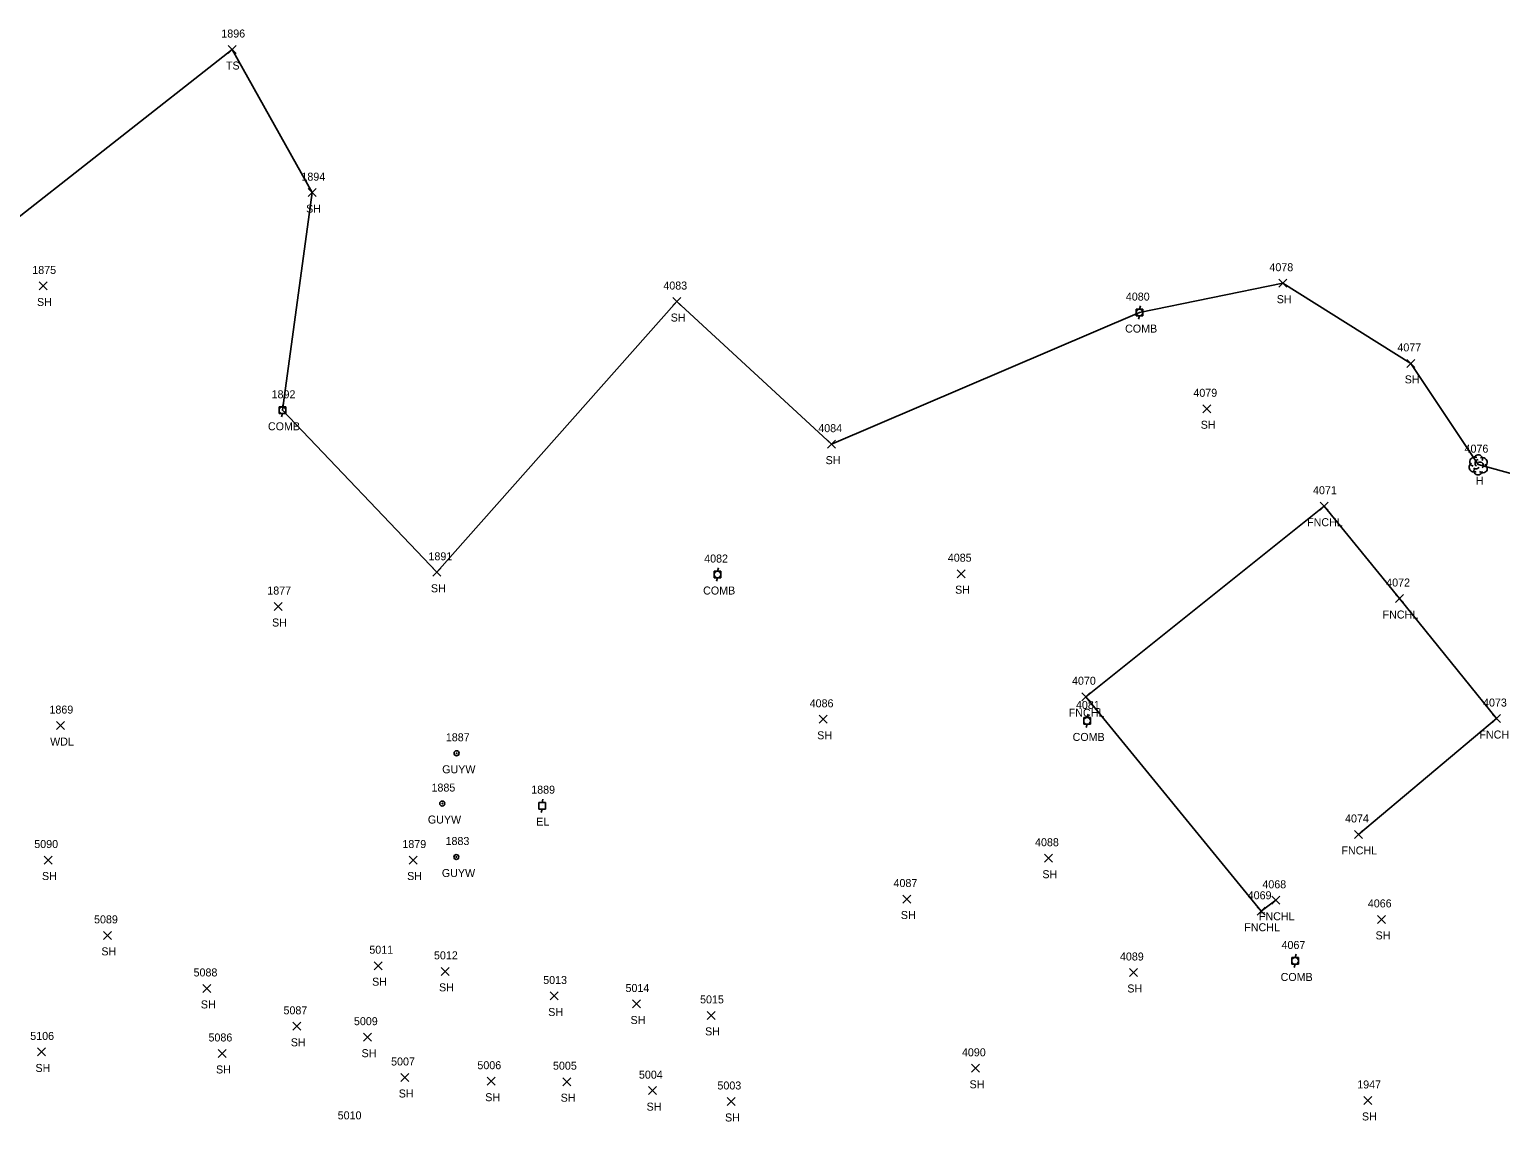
# Model space of a CAD drawing. Extents: x 1509053 to 1511576, y 400838 to 402572.
# Drawn here: x 1510281.3 to 1510649, y 401737.3 to 402010.4 of the extents above; entities that cross this region are included whole.
import ezdxf

# ---------------------------------------------------------------- set-up
doc = ezdxf.new("R2010")
doc.units = 0
for name, color, linetype in [('L_A', 7, 'Continuous'), ('L_I', 7, 'Continuous'), ('L_TIC', 7, 'Continuous'), ('LELB', 7, 'Continuous'), ('LFNC', 7, 'Continuous'), ('LSOGP', 7, 'Continuous'), ('LTD', 7, 'Continuous'), ('U_A', 7, 'Continuous'), ('U_I', 7, 'Continuous'), ('UEPT', 7, 'Continuous'), ('UP', 7, 'Continuous'), ('UPGW', 7, 'Continuous')]:
    doc.layers.add(name, color=color, linetype=linetype)

msp = doc.modelspace()

# ---------------------------------------------------------------- linework, layer by layer
at = {"layer": 'L_TIC'}
for points in [[(1510330.98, 402004.35), (1510332.98, 402006.35)], [(1510332.98, 402004.35), (1510330.98, 402006.35)], [(1510350.95, 401968.56), (1510352.95, 401970.56)], [(1510352.95, 401968.56), (1510350.95, 401970.56)], [(1510283.67, 401945.23), (1510285.67, 401947.23)], [(1510285.67, 401945.23), (1510283.67, 401947.23)], [(1510593.59, 401945.92), (1510595.59, 401947.92)], [(1510595.59, 401945.92), (1510593.59, 401947.92)], [(1510442.08, 401941.33), (1510444.08, 401943.33)], [(1510444.08, 401941.33), (1510442.08, 401943.33)], [(1510625.58, 401925.87), (1510627.58, 401927.87)], [(1510627.58, 401925.87), (1510625.58, 401927.87)], [(1510574.59, 401914.52), (1510576.59, 401916.52)], [(1510576.59, 401914.52), (1510574.59, 401916.52)], [(1510480.81, 401905.67), (1510482.81, 401907.67)], [(1510482.81, 401905.67), (1510480.81, 401907.67)], [(1510603.92, 401890.16), (1510605.92, 401892.16)], [(1510605.92, 401890.16), (1510603.92, 401892.16)], [(1510382.14, 401873.63), (1510384.14, 401875.63)], [(1510384.14, 401873.63), (1510382.14, 401875.63)], [(1510513.19, 401873.28), (1510515.19, 401875.28)], [(1510515.19, 401873.28), (1510513.19, 401875.28)], [(1510622.79, 401867.07), (1510624.79, 401869.07)], [(1510624.79, 401867.07), (1510622.79, 401869.07)], [(1510342.43, 401865.07), (1510344.43, 401867.07)], [(1510344.43, 401865.07), (1510342.43, 401867.07)], [(1510544.32, 401842.51), (1510546.32, 401844.51)], [(1510546.32, 401842.51), (1510544.32, 401844.51)], [(1510646.99, 401837.06), (1510648.99, 401839.06)], [(1510648.99, 401837.06), (1510646.99, 401839.06)], [(1510288.02, 401835.3), (1510290.02, 401837.3)], [(1510290.02, 401835.3), (1510288.02, 401837.3)], [(1510478.71, 401836.87), (1510480.71, 401838.87)], [(1510480.71, 401836.87), (1510478.71, 401838.87)], [(1510612.5, 401808.08), (1510614.5, 401810.08)], [(1510614.5, 401808.08), (1510612.5, 401810.08)], [(1510284.91, 401801.68), (1510286.91, 401803.68)], [(1510286.91, 401801.68), (1510284.91, 401803.68)], [(1510376.2, 401801.68), (1510378.2, 401803.68)], [(1510378.2, 401801.68), (1510376.2, 401803.68)], [(1510535, 401802.13), (1510537, 401804.13)], [(1510537, 401802.13), (1510535, 401804.13)], [(1510499.62, 401791.92), (1510501.62, 401793.92)], [(1510501.62, 401791.92), (1510499.62, 401793.92)], [(1510591.87, 401791.61), (1510593.87, 401793.61)], [(1510593.87, 401791.61), (1510591.87, 401793.61)], [(1510588.21, 401788.87), (1510590.21, 401790.87)], [(1510590.21, 401788.87), (1510588.21, 401790.87)], [(1510618.29, 401786.83), (1510620.29, 401788.83)], [(1510620.29, 401786.83), (1510618.29, 401788.83)], [(1510299.76, 401782.84), (1510301.76, 401784.84)], [(1510301.76, 401782.84), (1510299.76, 401784.84)], [(1510367.44, 401775.25), (1510369.44, 401777.25)], [(1510369.44, 401775.25), (1510367.44, 401777.25)], [(1510384.17, 401773.84), (1510386.17, 401775.84)], [(1510386.17, 401773.84), (1510384.17, 401775.84)], [(1510556.23, 401773.56), (1510558.23, 401775.56)], [(1510558.23, 401773.56), (1510556.23, 401775.56)], [(1510324.64, 401769.57), (1510326.64, 401771.57)], [(1510326.64, 401769.57), (1510324.64, 401771.57)], [(1510411.47, 401767.68), (1510413.47, 401769.68)], [(1510413.47, 401767.68), (1510411.47, 401769.68)], [(1510432.05, 401765.68), (1510434.05, 401767.68)], [(1510434.05, 401765.68), (1510432.05, 401767.68)], [(1510347.12, 401760.1), (1510349.12, 401762.1)], [(1510349.12, 401760.1), (1510347.12, 401762.1)], [(1510450.69, 401762.83), (1510452.69, 401764.83)], [(1510452.69, 401762.83), (1510450.69, 401764.83)], [(1510364.81, 401757.38), (1510366.81, 401759.38)], [(1510366.81, 401757.38), (1510364.81, 401759.38)], [(1510283.29, 401753.69), (1510285.29, 401755.69)], [(1510285.29, 401753.69), (1510283.29, 401755.69)], [(1510328.42, 401753.31), (1510330.42, 401755.31)], [(1510330.42, 401753.31), (1510328.42, 401755.31)], [(1510516.8, 401749.6), (1510518.8, 401751.6)], [(1510518.8, 401749.6), (1510516.8, 401751.6)], [(1510374.09, 401747.3), (1510376.09, 401749.3)], [(1510376.09, 401747.3), (1510374.09, 401749.3)], [(1510395.72, 401746.37), (1510397.72, 401748.37)], [(1510397.72, 401746.37), (1510395.72, 401748.37)], [(1510414.57, 401746.25), (1510416.57, 401748.25)], [(1510416.57, 401746.25), (1510414.57, 401748.25)], [(1510436.06, 401744.01), (1510438.06, 401746.01)], [(1510438.06, 401744.01), (1510436.06, 401746.01)], [(1510614.89, 401741.56), (1510616.89, 401743.56)], [(1510616.89, 401741.56), (1510614.89, 401743.56)], [(1510455.68, 401741.3), (1510457.68, 401743.3)], [(1510457.68, 401741.3), (1510455.68, 401743.3)]]:
    msp.add_lwpolyline(points, dxfattribs=at)
at = {"layer": 'LELB'}
msp.add_lwpolyline([(1510246.43, 401941.98), (1510272.01, 401958.33), (1510331.98, 402005.35)], dxfattribs=at)
at = {"layer": 'LFNC'}
msp.add_lwpolyline([(1510592.87, 401792.61), (1510589.21, 401789.87), (1510545.32, 401843.51), (1510604.92, 401891.16), (1510623.79, 401868.07), (1510647.99, 401838.06), (1510613.5, 401809.08)], dxfattribs=at)
at = {"layer": 'LSOGP'}
msp.add_lwpolyline([(1510659.15, 401897.28), (1510643.42, 401901.55), (1510626.58, 401926.87), (1510594.59, 401946.92), (1510558.78, 401939.57), (1510481.81, 401906.67), (1510443.08, 401942.33), (1510383.14, 401874.63), (1510344.5, 401915.14), (1510351.95, 401969.56), (1510331.98, 402005.35), (1510272.01, 401958.33)], dxfattribs=at)
at = {"layer": 'LTD'}
msp.add_line((1510643.42, 401901.55), (1510643.42, 401901.55), dxfattribs=at)
msp.add_line((1510643.42, 401901.55), (1510643.42, 401901.55), dxfattribs=at)
msp.add_arc((1510643.47, 401902.98), 1.05, 335.5272, 180.9563, dxfattribs=at)
for centre, major_axis, ratio, start_param, end_param in [((1510642.34, 401900.84), (0.58, -1.04), 0.959034, 3.141593, 6.283185), ((1510642.63, 401902.22), (1.21, -0.51), 0.895232, 1.570796, 4.712389), ((1510643.21, 401902.01), (-0.208, -0.792), 0.645439, 3.141593, 6.283185), ((1510643.92, 401901.38), (-0.5, 0.667), 0.989748, 3.141593, 6.283185), ((1510644.42, 401900.72), (-1.09, 0.79), 0.841452, 1.570796, 4.712389), ((1510644.46, 401902.13), (-1.14, -0.48), 0.949671, 1.570796, 4.712389), ((1510643.42, 401900.05), (0.26, 1.06), 0.942809, 1.570796, 4.712389), ((1510642.96, 401900.8), (-0.625, -0.083), 0.423636, 0, 3.141593)]:
    msp.add_ellipse(centre, major_axis=major_axis, ratio=ratio, start_param=start_param, end_param=end_param, dxfattribs=at)
at = {"layer": 'UEPT'}
for p, q in [((1510408.58, 401815.43), (1510408.58, 401817.1)), ((1510408.58, 401817.1), (1510410.25, 401817.1)), ((1510409.58, 401817.93), (1510409.41, 401817.1)), ((1510410.25, 401817.1), (1510410.25, 401815.43)), ((1510410.25, 401815.43), (1510408.58, 401815.43)), ((1510409.16, 401814.6), (1510409.41, 401815.43)), ((1510409.41, 401816.27), (1510409.41, 401816.27))]:
    msp.add_line(p, q, dxfattribs=at)
at = {"layer": 'UP'}
for p, q in [((1510557.95, 401938.74), (1510557.95, 401940.4)), ((1510557.95, 401940.4), (1510559.61, 401940.4)), ((1510559.61, 401938.74), (1510557.95, 401938.74)), ((1510558.53, 401937.9), (1510558.78, 401938.74)), ((1510559.03, 401941.24), (1510558.78, 401940.4)), ((1510558.78, 401939.57), (1510558.78, 401939.57)), ((1510559.61, 401940.4), (1510559.61, 401938.74)), ((1510344.75, 401916.81), (1510344.5, 401915.97)), ((1510343.67, 401914.31), (1510343.67, 401915.97)), ((1510343.67, 401915.97), (1510345.33, 401915.97)), ((1510345.33, 401914.31), (1510343.67, 401914.31)), ((1510344.25, 401913.47), (1510344.5, 401914.31)), ((1510344.5, 401915.14), (1510344.5, 401915.14)), ((1510345.33, 401915.97), (1510345.33, 401914.31)), ((1510452.46, 401873.24), (1510452.46, 401874.9)), ((1510452.46, 401874.9), (1510454.12, 401874.9)), ((1510454.12, 401873.24), (1510452.46, 401873.24)), ((1510453.04, 401872.4), (1510453.29, 401873.24)), ((1510453.54, 401875.74), (1510453.29, 401874.9)), ((1510453.29, 401874.07), (1510453.29, 401874.07)), ((1510454.12, 401874.9), (1510454.12, 401873.24)), ((1510545.91, 401839.13), (1510545.66, 401838.29)), ((1510544.83, 401836.63), (1510544.83, 401838.29)), ((1510544.83, 401838.29), (1510546.49, 401838.29)), ((1510546.49, 401836.63), (1510544.83, 401836.63)), ((1510545.41, 401835.79), (1510545.66, 401836.63)), ((1510545.66, 401837.46), (1510545.66, 401837.46)), ((1510546.49, 401838.29), (1510546.49, 401836.63)), ((1510596.83, 401776.61), (1510596.83, 401778.27)), ((1510596.83, 401778.27), (1510598.49, 401778.27)), ((1510598.49, 401776.61), (1510596.83, 401776.61)), ((1510597.41, 401775.77), (1510597.66, 401776.61)), ((1510597.91, 401779.11), (1510597.66, 401778.27)), ((1510597.66, 401777.44), (1510597.66, 401777.44)), ((1510598.49, 401778.27), (1510598.49, 401776.61))]:
    msp.add_line(p, q, dxfattribs=at)
for centre in [(1510558.78, 401939.57), (1510344.5, 401915.14), (1510453.29, 401874.07), (1510545.66, 401837.46), (1510597.66, 401777.44)]:
    msp.add_circle(centre, 0.833, dxfattribs=at)
at = {"layer": 'UPGW'}
for centre, radius in [((1510388.06, 401829.37), 0.625), ((1510388.06, 401829.37), 0.0833), ((1510384.47, 401816.8), 0.625), ((1510384.47, 401816.8), 0.0833), ((1510387.98, 401803.43), 0.625), ((1510387.98, 401803.43), 0.0833)]:
    msp.add_circle(centre, radius, dxfattribs=at)

# ---------------------------------------------------------------- texts
at = {"layer": 'L_A'}
for s, p in [('TS', (1510330.39, 402000.35)), ('SH', (1510350.44, 401964.56)), ('SH', (1510283.16, 401941.23)), ('SH', (1510593.08, 401941.92)), ('SH', (1510441.57, 401937.33)), ('SH', (1510625.07, 401921.87)), ('SH', (1510574.08, 401910.52)), ('SH', (1510480.3, 401901.67)), ('H', (1510642.85, 401896.55)), ('FNCHL', (1510600.67, 401886.16)), ('SH', (1510381.63, 401869.63)), ('SH', (1510512.68, 401869.28)), ('FNCHL', (1510619.54, 401863.07)), ('SH', (1510341.91, 401861.07)), ('FNCHL', (1510541.07, 401838.51)), ('WDL', (1510286.44, 401831.3)), ('SH', (1510478.2, 401832.87)), ('FNCHL', (1510643.74, 401833.06)), ('FNCHL', (1510609.25, 401804.08)), ('SH', (1510284.4, 401797.68)), ('SH', (1510375.69, 401797.68)), ('SH', (1510534.49, 401798.13)), ('SH', (1510499.11, 401787.92)), ('FNCHL', (1510588.62, 401787.61)), ('FNCHL', (1510584.96, 401784.87)), ('SH', (1510617.78, 401782.83)), ('SH', (1510299.25, 401778.84)), ('SH', (1510366.93, 401771.25)), ('SH', (1510383.66, 401769.84)), ('SH', (1510555.72, 401769.56)), ('SH', (1510324.12, 401765.57)), ('SH', (1510410.96, 401763.68)), ('SH', (1510431.54, 401761.68)), ('SH', (1510346.61, 401756.1)), ('SH', (1510450.18, 401758.83)), ('SH', (1510364.3, 401753.38)), ('SH', (1510282.78, 401749.69)), ('SH', (1510327.91, 401749.31)), ('SH', (1510516.29, 401745.6)), ('SH', (1510373.58, 401743.3)), ('SH', (1510395.21, 401742.37)), ('SH', (1510414.06, 401742.25)), ('SH', (1510435.55, 401740.01)), ('SH', (1510455.16, 401737.3)), ('SH', (1510614.38, 401737.56))]:
    msp.add_text(s, height=2, dxfattribs=at).set_placement(p)
at = {"layer": 'L_I'}
for s, p in [('1896', (1510329.24, 402008.35)), ('1894', (1510349.26, 401972.56)), ('1875', (1510281.98, 401949.23)), ('4078', (1510591.25, 401949.92)), ('4083', (1510439.74, 401945.33)), ('4077', (1510623.24, 401929.87)), ('4079', (1510572.24, 401918.52)), ('4084', (1510478.47, 401909.67)), ('4076', (1510640.03, 401904.55)), ('4071', (1510602.15, 401894.16)), ('1891', (1510381.02, 401877.63)), ('4085', (1510510.85, 401877.28)), ('4072', (1510620.45, 401871.07)), ('1877', (1510340.73, 401869.07)), ('4070', (1510541.9, 401846.51)), ('4086', (1510476.32, 401840.87)), ('4073', (1510644.65, 401841.06)), ('1869', (1510286.27, 401839.3)), ('4074', (1510610.16, 401812.08)), ('5090', (1510282.48, 401805.68)), ('1879', (1510374.5, 401805.68)), ('4088', (1510532.66, 401806.13)), ('4087', (1510497.28, 401795.92)), ('4069', (1510585.82, 401792.87)), ('4068', (1510589.49, 401795.61)), ('4066', (1510615.85, 401790.83)), ('5089', (1510297.42, 401786.84)), ('5011', (1510366.24, 401779.25)), ('5012', (1510382.4, 401777.84)), ('4089', (1510553.88, 401777.56)), ('5088', (1510322.3, 401773.57)), ('5013', (1510409.7, 401771.68)), ('5014', (1510430.28, 401769.68)), ('5087', (1510344.78, 401764.1)), ('5015', (1510448.92, 401766.83)), ('5009', (1510362.39, 401761.38)), ('5106', (1510281.47, 401757.69)), ('5086', (1510326.03, 401757.31)), ('4090', (1510514.38, 401753.6)), ('5007', (1510371.68, 401751.3)), ('5006', (1510393.25, 401750.37)), ('5005', (1510412.15, 401750.25)), ('5004', (1510433.64, 401748.01)), ('5003', (1510453.26, 401745.3)), ('1947', (1510613.2, 401745.56)), ('5010', (1510358.33, 401737.83))]:
    msp.add_text(s, height=2, dxfattribs=at).set_placement(p)
at = {"layer": 'U_A'}
for s, p in [('COMB', (1510555.17, 401934.57)), ('COMB', (1510340.89, 401910.14)), ('COMB', (1510449.68, 401869.07)), ('COMB', (1510542.05, 401832.46)), ('GUYW', (1510384.45, 401824.37)), ('GUYW', (1510380.87, 401811.8)), ('EL', (1510407.95, 401811.27)), ('GUYW', (1510384.37, 401798.43)), ('COMB', (1510594.05, 401772.44))]:
    msp.add_text(s, height=2, dxfattribs=at).set_placement(p)
at = {"layer": 'U_I'}
for s, p in [('4080', (1510555.36, 401942.57)), ('1892', (1510341.81, 401918.14)), ('4082', (1510449.95, 401877.07)), ('4081', (1510542.89, 401840.46)), ('1887', (1510385.36, 401832.37)), ('1885', (1510381.78, 401819.8)), ('1889', (1510406.71, 401819.27)), ('1883', (1510385.29, 401806.43)), ('4067', (1510594.28, 401780.44))]:
    msp.add_text(s, height=2, dxfattribs=at).set_placement(p)

doc.saveas('drawing.dxf')
